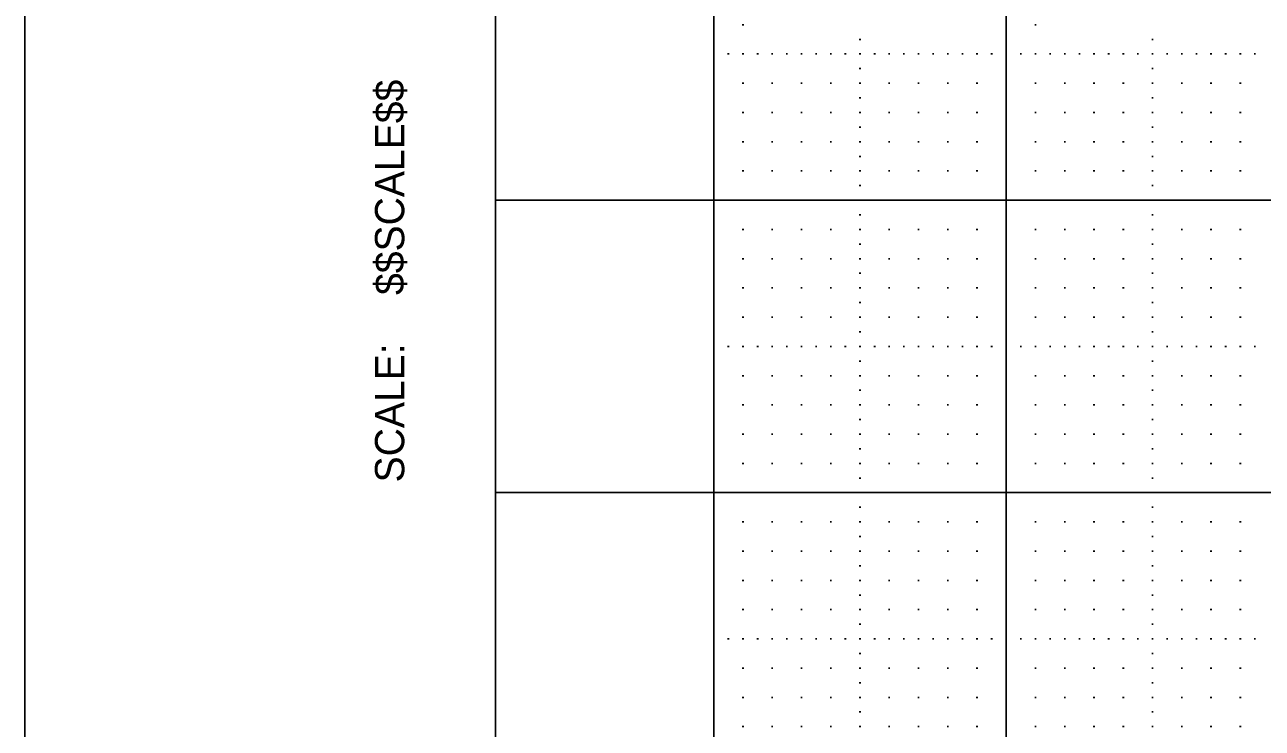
# Model space of a CAD drawing. Extents: x -1.3 to 32.7, y -0.7 to 21.3.
# Drawn here: x -1.263 to 2.967, y 2.487 to 4.893 of the extents above; entities that cross this region are included whole.
import ezdxf

# ---------------------------------------------------------------- set-up
doc = ezdxf.new("R2010")
doc.units = 0
for name, color, linetype in [('Level 1', 7, 'Continuous'), ('Level 5', 7, 'Continuous'), ('Level 63', 7, 'Continuous'), ('R_Border_Dark', 7, 'Continuous')]:
    doc.layers.add(name, color=color, linetype=linetype)

msp = doc.modelspace()

# ---------------------------------------------------------------- linework, layer by layer
at = {"layer": 'Level 1'}
for p, q in [((-1.263, 21.273), (-1.263, -0.727)), ((0.3463, -0.001), (0.3463, 20.545))]:
    msp.add_line(p, q, dxfattribs=at)
at = {"layer": 'Level 5'}
for p, q in [((1.1898, 4.893), (1.1948, 4.893)), ((2.1898, 4.893), (2.1948, 4.893)), ((1.5898, 4.843), (1.5948, 4.843)), ((2.5898, 4.843), (2.5948, 4.843)), ((1.1398, 4.793), (1.1448, 4.793)), ((1.1898, 4.793), (1.1948, 4.793)), ((1.2398, 4.793), (1.2448, 4.793)), ((1.2898, 4.793), (1.2948, 4.793)), ((1.3398, 4.793), (1.3448, 4.793)), ((1.3898, 4.793), (1.3948, 4.793)), ((1.4398, 4.793), (1.4448, 4.793)), ((1.4898, 4.793), (1.4948, 4.793)), ((1.5398, 4.793), (1.5448, 4.793)), ((1.5898, 4.793), (1.5948, 4.793)), ((1.6398, 4.793), (1.6448, 4.793)), ((1.6898, 4.793), (1.6948, 4.793)), ((1.7398, 4.793), (1.7448, 4.793)), ((1.7898, 4.793), (1.7948, 4.793)), ((1.8398, 4.793), (1.8448, 4.793)), ((1.8898, 4.793), (1.8948, 4.793)), ((1.9398, 4.793), (1.9448, 4.793)), ((1.9898, 4.793), (1.9948, 4.793)), ((2.0398, 4.793), (2.0448, 4.793)), ((2.1398, 4.793), (2.1448, 4.793)), ((2.1898, 4.793), (2.1948, 4.793)), ((2.2398, 4.793), (2.2448, 4.793)), ((2.2898, 4.793), (2.2948, 4.793)), ((2.3398, 4.793), (2.3448, 4.793)), ((2.3898, 4.793), (2.3948, 4.793)), ((2.4398, 4.793), (2.4448, 4.793)), ((2.4898, 4.793), (2.4948, 4.793)), ((2.5398, 4.793), (2.5448, 4.793)), ((2.5898, 4.793), (2.5948, 4.793)), ((2.6398, 4.793), (2.6448, 4.793)), ((2.6898, 4.793), (2.6948, 4.793)), ((2.7398, 4.793), (2.7448, 4.793)), ((2.7898, 4.793), (2.7948, 4.793)), ((2.8398, 4.793), (2.8448, 4.793)), ((2.8898, 4.793), (2.8948, 4.793)), ((2.9398, 4.793), (2.9448, 4.793)), ((1.5898, 4.743), (1.5948, 4.743)), ((2.5898, 4.743), (2.5948, 4.743)), ((1.1898, 4.693), (1.1948, 4.693)), ((1.2898, 4.693), (1.2948, 4.693)), ((1.3898, 4.693), (1.3948, 4.693)), ((1.4898, 4.693), (1.4948, 4.693)), ((1.5898, 4.693), (1.5948, 4.693)), ((1.6898, 4.693), (1.6948, 4.693)), ((1.7898, 4.693), (1.7948, 4.693)), ((1.8898, 4.693), (1.8948, 4.693)), ((1.9898, 4.693), (1.9948, 4.693)), ((2.1898, 4.693), (2.1948, 4.693)), ((2.2898, 4.693), (2.2948, 4.693)), ((2.3898, 4.693), (2.3948, 4.693)), ((2.4898, 4.693), (2.4948, 4.693)), ((2.5898, 4.693), (2.5948, 4.693)), ((2.6898, 4.693), (2.6948, 4.693)), ((2.7898, 4.693), (2.7948, 4.693)), ((2.8898, 4.693), (2.8948, 4.693)), ((1.5898, 4.643), (1.5948, 4.643)), ((2.5898, 4.643), (2.5948, 4.643)), ((1.1898, 4.593), (1.1948, 4.593)), ((1.2898, 4.593), (1.2948, 4.593)), ((1.3898, 4.593), (1.3948, 4.593)), ((1.4898, 4.593), (1.4948, 4.593)), ((1.5898, 4.593), (1.5948, 4.593)), ((1.6898, 4.593), (1.6948, 4.593)), ((1.7898, 4.593), (1.7948, 4.593)), ((1.8898, 4.593), (1.8948, 4.593)), ((1.9898, 4.593), (1.9948, 4.593)), ((2.1898, 4.593), (2.1948, 4.593)), ((2.2898, 4.593), (2.2948, 4.593)), ((2.3898, 4.593), (2.3948, 4.593)), ((2.4898, 4.593), (2.4948, 4.593)), ((2.5898, 4.593), (2.5948, 4.593)), ((2.6898, 4.593), (2.6948, 4.593)), ((2.7898, 4.593), (2.7948, 4.593)), ((2.8898, 4.593), (2.8948, 4.593)), ((1.5898, 4.543), (1.5948, 4.543)), ((2.5898, 4.543), (2.5948, 4.543)), ((1.1898, 4.493), (1.1948, 4.493)), ((1.2898, 4.493), (1.2948, 4.493)), ((1.3898, 4.493), (1.3948, 4.493)), ((1.4898, 4.493), (1.4948, 4.493)), ((1.5898, 4.493), (1.5948, 4.493)), ((1.6898, 4.493), (1.6948, 4.493)), ((1.7898, 4.493), (1.7948, 4.493)), ((1.8898, 4.493), (1.8948, 4.493)), ((1.9898, 4.493), (1.9948, 4.493)), ((2.1898, 4.493), (2.1948, 4.493)), ((2.2898, 4.493), (2.2948, 4.493)), ((2.3898, 4.493), (2.3948, 4.493)), ((2.4898, 4.493), (2.4948, 4.493)), ((2.5898, 4.493), (2.5948, 4.493)), ((2.6898, 4.493), (2.6948, 4.493)), ((2.7898, 4.493), (2.7948, 4.493)), ((2.8898, 4.493), (2.8948, 4.493)), ((1.5898, 4.443), (1.5948, 4.443)), ((2.5898, 4.443), (2.5948, 4.443)), ((1.1898, 4.393), (1.1948, 4.393)), ((1.2898, 4.393), (1.2948, 4.393)), ((1.3898, 4.393), (1.3948, 4.393)), ((1.4898, 4.393), (1.4948, 4.393)), ((1.5898, 4.393), (1.5948, 4.393)), ((1.6898, 4.393), (1.6948, 4.393)), ((1.7898, 4.393), (1.7948, 4.393)), ((1.8898, 4.393), (1.8948, 4.393)), ((1.9898, 4.393), (1.9948, 4.393)), ((2.1898, 4.393), (2.1948, 4.393)), ((2.2898, 4.393), (2.2948, 4.393)), ((2.3898, 4.393), (2.3948, 4.393)), ((2.4898, 4.393), (2.4948, 4.393)), ((2.5898, 4.393), (2.5948, 4.393)), ((2.6898, 4.393), (2.6948, 4.393)), ((2.7898, 4.393), (2.7948, 4.393)), ((2.8898, 4.393), (2.8948, 4.393)), ((1.5898, 4.343), (1.5948, 4.343)), ((2.5898, 4.343), (2.5948, 4.343)), ((1.5898, 4.243), (1.5948, 4.243)), ((2.5898, 4.243), (2.5948, 4.243)), ((1.1898, 4.193), (1.1948, 4.193)), ((1.2898, 4.193), (1.2948, 4.193)), ((1.3898, 4.193), (1.3948, 4.193)), ((1.4898, 4.193), (1.4948, 4.193)), ((1.5898, 4.193), (1.5948, 4.193)), ((1.6898, 4.193), (1.6948, 4.193)), ((1.7898, 4.193), (1.7948, 4.193)), ((1.8898, 4.193), (1.8948, 4.193)), ((1.9898, 4.193), (1.9948, 4.193)), ((2.1898, 4.193), (2.1948, 4.193)), ((2.2898, 4.193), (2.2948, 4.193)), ((2.3898, 4.193), (2.3948, 4.193)), ((2.4898, 4.193), (2.4948, 4.193)), ((2.5898, 4.193), (2.5948, 4.193)), ((2.6898, 4.193), (2.6948, 4.193)), ((2.7898, 4.193), (2.7948, 4.193)), ((2.8898, 4.193), (2.8948, 4.193)), ((1.5898, 4.143), (1.5948, 4.143)), ((2.5898, 4.143), (2.5948, 4.143)), ((1.1898, 4.093), (1.1948, 4.093)), ((1.2898, 4.093), (1.2948, 4.093)), ((1.3898, 4.093), (1.3948, 4.093)), ((1.4898, 4.093), (1.4948, 4.093)), ((1.5898, 4.093), (1.5948, 4.093)), ((1.6898, 4.093), (1.6948, 4.093)), ((1.7898, 4.093), (1.7948, 4.093)), ((1.8898, 4.093), (1.8948, 4.093)), ((1.9898, 4.093), (1.9948, 4.093)), ((2.1898, 4.093), (2.1948, 4.093)), ((2.2898, 4.093), (2.2948, 4.093)), ((2.3898, 4.093), (2.3948, 4.093)), ((2.4898, 4.093), (2.4948, 4.093)), ((2.5898, 4.093), (2.5948, 4.093)), ((2.6898, 4.093), (2.6948, 4.093)), ((2.7898, 4.093), (2.7948, 4.093)), ((2.8898, 4.093), (2.8948, 4.093)), ((1.5898, 4.043), (1.5948, 4.043)), ((2.5898, 4.043), (2.5948, 4.043)), ((1.1898, 3.993), (1.1948, 3.993)), ((1.2898, 3.993), (1.2948, 3.993)), ((1.3898, 3.993), (1.3948, 3.993)), ((1.4898, 3.993), (1.4948, 3.993)), ((1.5898, 3.993), (1.5948, 3.993)), ((1.6898, 3.993), (1.6948, 3.993)), ((1.7898, 3.993), (1.7948, 3.993)), ((1.8898, 3.993), (1.8948, 3.993)), ((1.9898, 3.993), (1.9948, 3.993)), ((2.1898, 3.993), (2.1948, 3.993)), ((2.2898, 3.993), (2.2948, 3.993)), ((2.3898, 3.993), (2.3948, 3.993)), ((2.4898, 3.993), (2.4948, 3.993)), ((2.5898, 3.993), (2.5948, 3.993)), ((2.6898, 3.993), (2.6948, 3.993)), ((2.7898, 3.993), (2.7948, 3.993)), ((2.8898, 3.993), (2.8948, 3.993)), ((1.5898, 3.943), (1.5948, 3.943)), ((2.5898, 3.943), (2.5948, 3.943)), ((1.1898, 3.893), (1.1948, 3.893)), ((1.2898, 3.893), (1.2948, 3.893)), ((1.3898, 3.893), (1.3948, 3.893)), ((1.4898, 3.893), (1.4948, 3.893)), ((1.5898, 3.893), (1.5948, 3.893)), ((1.6898, 3.893), (1.6948, 3.893)), ((1.7898, 3.893), (1.7948, 3.893)), ((1.8898, 3.893), (1.8948, 3.893)), ((1.9898, 3.893), (1.9948, 3.893)), ((2.1898, 3.893), (2.1948, 3.893)), ((2.2898, 3.893), (2.2948, 3.893)), ((2.3898, 3.893), (2.3948, 3.893)), ((2.4898, 3.893), (2.4948, 3.893)), ((2.5898, 3.893), (2.5948, 3.893)), ((2.6898, 3.893), (2.6948, 3.893)), ((2.7898, 3.893), (2.7948, 3.893)), ((2.8898, 3.893), (2.8948, 3.893)), ((1.5898, 3.843), (1.5948, 3.843)), ((2.5898, 3.843), (2.5948, 3.843)), ((1.1398, 3.793), (1.1448, 3.793)), ((1.1898, 3.793), (1.1948, 3.793)), ((1.2398, 3.793), (1.2448, 3.793)), ((1.2898, 3.793), (1.2948, 3.793)), ((1.3398, 3.793), (1.3448, 3.793)), ((1.3898, 3.793), (1.3948, 3.793)), ((1.4398, 3.793), (1.4448, 3.793)), ((1.4898, 3.793), (1.4948, 3.793)), ((1.5398, 3.793), (1.5448, 3.793)), ((1.5898, 3.793), (1.5948, 3.793)), ((1.6398, 3.793), (1.6448, 3.793)), ((1.6898, 3.793), (1.6948, 3.793)), ((1.7398, 3.793), (1.7448, 3.793)), ((1.7898, 3.793), (1.7948, 3.793)), ((1.8398, 3.793), (1.8448, 3.793)), ((1.8898, 3.793), (1.8948, 3.793)), ((1.9398, 3.793), (1.9448, 3.793)), ((1.9898, 3.793), (1.9948, 3.793)), ((2.0398, 3.793), (2.0448, 3.793)), ((2.1398, 3.793), (2.1448, 3.793)), ((2.1898, 3.793), (2.1948, 3.793)), ((2.2398, 3.793), (2.2448, 3.793)), ((2.2898, 3.793), (2.2948, 3.793)), ((2.3398, 3.793), (2.3448, 3.793)), ((2.3898, 3.793), (2.3948, 3.793)), ((2.4398, 3.793), (2.4448, 3.793)), ((2.4898, 3.793), (2.4948, 3.793)), ((2.5398, 3.793), (2.5448, 3.793)), ((2.5898, 3.793), (2.5948, 3.793)), ((2.6398, 3.793), (2.6448, 3.793)), ((2.6898, 3.793), (2.6948, 3.793)), ((2.7398, 3.793), (2.7448, 3.793)), ((2.7898, 3.793), (2.7948, 3.793)), ((2.8398, 3.793), (2.8448, 3.793)), ((2.8898, 3.793), (2.8948, 3.793)), ((2.9398, 3.793), (2.9448, 3.793)), ((1.5898, 3.743), (1.5948, 3.743)), ((2.5898, 3.743), (2.5948, 3.743)), ((1.1898, 3.693), (1.1948, 3.693)), ((1.2898, 3.693), (1.2948, 3.693)), ((1.3898, 3.693), (1.3948, 3.693)), ((1.4898, 3.693), (1.4948, 3.693)), ((1.5898, 3.693), (1.5948, 3.693)), ((1.6898, 3.693), (1.6948, 3.693)), ((1.7898, 3.693), (1.7948, 3.693)), ((1.8898, 3.693), (1.8948, 3.693)), ((1.9898, 3.693), (1.9948, 3.693)), ((2.1898, 3.693), (2.1948, 3.693)), ((2.2898, 3.693), (2.2948, 3.693)), ((2.3898, 3.693), (2.3948, 3.693)), ((2.4898, 3.693), (2.4948, 3.693)), ((2.5898, 3.693), (2.5948, 3.693)), ((2.6898, 3.693), (2.6948, 3.693)), ((2.7898, 3.693), (2.7948, 3.693)), ((2.8898, 3.693), (2.8948, 3.693)), ((1.5898, 3.643), (1.5948, 3.643)), ((2.5898, 3.643), (2.5948, 3.643)), ((1.1898, 3.593), (1.1948, 3.593)), ((1.2898, 3.593), (1.2948, 3.593)), ((1.3898, 3.593), (1.3948, 3.593)), ((1.4898, 3.593), (1.4948, 3.593)), ((1.5898, 3.593), (1.5948, 3.593)), ((1.6898, 3.593), (1.6948, 3.593)), ((1.7898, 3.593), (1.7948, 3.593)), ((1.8898, 3.593), (1.8948, 3.593)), ((1.9898, 3.593), (1.9948, 3.593)), ((2.1898, 3.593), (2.1948, 3.593)), ((2.2898, 3.593), (2.2948, 3.593)), ((2.3898, 3.593), (2.3948, 3.593)), ((2.4898, 3.593), (2.4948, 3.593)), ((2.5898, 3.593), (2.5948, 3.593)), ((2.6898, 3.593), (2.6948, 3.593)), ((2.7898, 3.593), (2.7948, 3.593)), ((2.8898, 3.593), (2.8948, 3.593)), ((1.5898, 3.543), (1.5948, 3.543)), ((2.5898, 3.543), (2.5948, 3.543)), ((1.1898, 3.493), (1.1948, 3.493)), ((1.2898, 3.493), (1.2948, 3.493)), ((1.3898, 3.493), (1.3948, 3.493)), ((1.4898, 3.493), (1.4948, 3.493)), ((1.5898, 3.493), (1.5948, 3.493)), ((1.6898, 3.493), (1.6948, 3.493)), ((1.7898, 3.493), (1.7948, 3.493)), ((1.8898, 3.493), (1.8948, 3.493)), ((1.9898, 3.493), (1.9948, 3.493)), ((2.1898, 3.493), (2.1948, 3.493)), ((2.2898, 3.493), (2.2948, 3.493)), ((2.3898, 3.493), (2.3948, 3.493)), ((2.4898, 3.493), (2.4948, 3.493)), ((2.5898, 3.493), (2.5948, 3.493)), ((2.6898, 3.493), (2.6948, 3.493)), ((2.7898, 3.493), (2.7948, 3.493)), ((2.8898, 3.493), (2.8948, 3.493)), ((1.5898, 3.443), (1.5948, 3.443)), ((2.5898, 3.443), (2.5948, 3.443)), ((1.1898, 3.393), (1.1948, 3.393)), ((1.2898, 3.393), (1.2948, 3.393)), ((1.3898, 3.393), (1.3948, 3.393)), ((1.4898, 3.393), (1.4948, 3.393)), ((1.5898, 3.393), (1.5948, 3.393)), ((1.6898, 3.393), (1.6948, 3.393)), ((1.7898, 3.393), (1.7948, 3.393)), ((1.8898, 3.393), (1.8948, 3.393)), ((1.9898, 3.393), (1.9948, 3.393)), ((2.1898, 3.393), (2.1948, 3.393)), ((2.2898, 3.393), (2.2948, 3.393)), ((2.3898, 3.393), (2.3948, 3.393)), ((2.4898, 3.393), (2.4948, 3.393)), ((2.5898, 3.393), (2.5948, 3.393)), ((2.6898, 3.393), (2.6948, 3.393)), ((2.7898, 3.393), (2.7948, 3.393)), ((2.8898, 3.393), (2.8948, 3.393)), ((1.5898, 3.343), (1.5948, 3.343)), ((2.5898, 3.343), (2.5948, 3.343)), ((1.5898, 3.243), (1.5948, 3.243)), ((2.5898, 3.243), (2.5948, 3.243)), ((1.1898, 3.193), (1.1948, 3.193)), ((1.2898, 3.193), (1.2948, 3.193)), ((1.3898, 3.193), (1.3948, 3.193)), ((1.4898, 3.193), (1.4948, 3.193)), ((1.5898, 3.193), (1.5948, 3.193)), ((1.6898, 3.193), (1.6948, 3.193)), ((1.7898, 3.193), (1.7948, 3.193)), ((1.8898, 3.193), (1.8948, 3.193)), ((1.9898, 3.193), (1.9948, 3.193)), ((2.1898, 3.193), (2.1948, 3.193)), ((2.2898, 3.193), (2.2948, 3.193)), ((2.3898, 3.193), (2.3948, 3.193)), ((2.4898, 3.193), (2.4948, 3.193)), ((2.5898, 3.193), (2.5948, 3.193)), ((2.6898, 3.193), (2.6948, 3.193)), ((2.7898, 3.193), (2.7948, 3.193)), ((2.8898, 3.193), (2.8948, 3.193)), ((1.5898, 3.143), (1.5948, 3.143)), ((2.5898, 3.143), (2.5948, 3.143)), ((1.1898, 3.093), (1.1948, 3.093)), ((1.2898, 3.093), (1.2948, 3.093)), ((1.3898, 3.093), (1.3948, 3.093)), ((1.4898, 3.093), (1.4948, 3.093)), ((1.5898, 3.093), (1.5948, 3.093)), ((1.6898, 3.093), (1.6948, 3.093)), ((1.7898, 3.093), (1.7948, 3.093)), ((1.8898, 3.093), (1.8948, 3.093)), ((1.9898, 3.093), (1.9948, 3.093)), ((2.1898, 3.093), (2.1948, 3.093)), ((2.2898, 3.093), (2.2948, 3.093)), ((2.3898, 3.093), (2.3948, 3.093)), ((2.4898, 3.093), (2.4948, 3.093)), ((2.5898, 3.093), (2.5948, 3.093)), ((2.6898, 3.093), (2.6948, 3.093)), ((2.7898, 3.093), (2.7948, 3.093)), ((2.8898, 3.093), (2.8948, 3.093)), ((1.5898, 3.043), (1.5948, 3.043)), ((2.5898, 3.043), (2.5948, 3.043)), ((1.1898, 2.993), (1.1948, 2.993)), ((1.2898, 2.993), (1.2948, 2.993)), ((1.3898, 2.993), (1.3948, 2.993)), ((1.4898, 2.993), (1.4948, 2.993)), ((1.5898, 2.993), (1.5948, 2.993)), ((1.6898, 2.993), (1.6948, 2.993)), ((1.7898, 2.993), (1.7948, 2.993)), ((1.8898, 2.993), (1.8948, 2.993)), ((1.9898, 2.993), (1.9948, 2.993)), ((2.1898, 2.993), (2.1948, 2.993)), ((2.2898, 2.993), (2.2948, 2.993)), ((2.3898, 2.993), (2.3948, 2.993)), ((2.4898, 2.993), (2.4948, 2.993)), ((2.5898, 2.993), (2.5948, 2.993)), ((2.6898, 2.993), (2.6948, 2.993)), ((2.7898, 2.993), (2.7948, 2.993)), ((2.8898, 2.993), (2.8948, 2.993)), ((1.5898, 2.943), (1.5948, 2.943)), ((2.5898, 2.943), (2.5948, 2.943)), ((1.1898, 2.893), (1.1948, 2.893)), ((1.2898, 2.893), (1.2948, 2.893)), ((1.3898, 2.893), (1.3948, 2.893)), ((1.4898, 2.893), (1.4948, 2.893)), ((1.5898, 2.893), (1.5948, 2.893)), ((1.6898, 2.893), (1.6948, 2.893)), ((1.7898, 2.893), (1.7948, 2.893)), ((1.8898, 2.893), (1.8948, 2.893)), ((1.9898, 2.893), (1.9948, 2.893)), ((2.1898, 2.893), (2.1948, 2.893)), ((2.2898, 2.893), (2.2948, 2.893)), ((2.3898, 2.893), (2.3948, 2.893)), ((2.4898, 2.893), (2.4948, 2.893)), ((2.5898, 2.893), (2.5948, 2.893)), ((2.6898, 2.893), (2.6948, 2.893)), ((2.7898, 2.893), (2.7948, 2.893)), ((2.8898, 2.893), (2.8948, 2.893)), ((1.5898, 2.843), (1.5948, 2.843)), ((2.5898, 2.843), (2.5948, 2.843)), ((1.1398, 2.793), (1.1448, 2.793)), ((1.1898, 2.793), (1.1948, 2.793)), ((1.2398, 2.793), (1.2448, 2.793)), ((1.2898, 2.793), (1.2948, 2.793)), ((1.3398, 2.793), (1.3448, 2.793)), ((1.3898, 2.793), (1.3948, 2.793)), ((1.4398, 2.793), (1.4448, 2.793)), ((1.4898, 2.793), (1.4948, 2.793)), ((1.5398, 2.793), (1.5448, 2.793)), ((1.5898, 2.793), (1.5948, 2.793)), ((1.6398, 2.793), (1.6448, 2.793)), ((1.6898, 2.793), (1.6948, 2.793)), ((1.7398, 2.793), (1.7448, 2.793)), ((1.7898, 2.793), (1.7948, 2.793)), ((1.8398, 2.793), (1.8448, 2.793)), ((1.8898, 2.793), (1.8948, 2.793)), ((1.9398, 2.793), (1.9448, 2.793)), ((1.9898, 2.793), (1.9948, 2.793)), ((2.0398, 2.793), (2.0448, 2.793)), ((2.1398, 2.793), (2.1448, 2.793)), ((2.1898, 2.793), (2.1948, 2.793)), ((2.2398, 2.793), (2.2448, 2.793)), ((2.2898, 2.793), (2.2948, 2.793)), ((2.3398, 2.793), (2.3448, 2.793)), ((2.3898, 2.793), (2.3948, 2.793)), ((2.4398, 2.793), (2.4448, 2.793)), ((2.4898, 2.793), (2.4948, 2.793)), ((2.5398, 2.793), (2.5448, 2.793)), ((2.5898, 2.793), (2.5948, 2.793)), ((2.6398, 2.793), (2.6448, 2.793)), ((2.6898, 2.793), (2.6948, 2.793)), ((2.7398, 2.793), (2.7448, 2.793)), ((2.7898, 2.793), (2.7948, 2.793)), ((2.8398, 2.793), (2.8448, 2.793)), ((2.8898, 2.793), (2.8948, 2.793)), ((2.9398, 2.793), (2.9448, 2.793)), ((1.5898, 2.743), (1.5948, 2.743)), ((2.5898, 2.743), (2.5948, 2.743)), ((1.1898, 2.693), (1.1948, 2.693)), ((1.2898, 2.693), (1.2948, 2.693)), ((1.3898, 2.693), (1.3948, 2.693)), ((1.4898, 2.693), (1.4948, 2.693)), ((1.5898, 2.693), (1.5948, 2.693)), ((1.6898, 2.693), (1.6948, 2.693)), ((1.7898, 2.693), (1.7948, 2.693)), ((1.8898, 2.693), (1.8948, 2.693)), ((1.9898, 2.693), (1.9948, 2.693)), ((2.1898, 2.693), (2.1948, 2.693)), ((2.2898, 2.693), (2.2948, 2.693)), ((2.3898, 2.693), (2.3948, 2.693)), ((2.4898, 2.693), (2.4948, 2.693)), ((2.5898, 2.693), (2.5948, 2.693)), ((2.6898, 2.693), (2.6948, 2.693)), ((2.7898, 2.693), (2.7948, 2.693)), ((2.8898, 2.693), (2.8948, 2.693)), ((1.5898, 2.643), (1.5948, 2.643)), ((2.5898, 2.643), (2.5948, 2.643)), ((1.1898, 2.593), (1.1948, 2.593)), ((1.2898, 2.593), (1.2948, 2.593)), ((1.3898, 2.593), (1.3948, 2.593)), ((1.4898, 2.593), (1.4948, 2.593)), ((1.5898, 2.593), (1.5948, 2.593)), ((1.6898, 2.593), (1.6948, 2.593)), ((1.7898, 2.593), (1.7948, 2.593)), ((1.8898, 2.593), (1.8948, 2.593)), ((1.9898, 2.593), (1.9948, 2.593)), ((2.1898, 2.593), (2.1948, 2.593)), ((2.2898, 2.593), (2.2948, 2.593)), ((2.3898, 2.593), (2.3948, 2.593)), ((2.4898, 2.593), (2.4948, 2.593)), ((2.5898, 2.593), (2.5948, 2.593)), ((2.6898, 2.593), (2.6948, 2.593)), ((2.7898, 2.593), (2.7948, 2.593)), ((2.8898, 2.593), (2.8948, 2.593)), ((1.5898, 2.543), (1.5948, 2.543)), ((2.5898, 2.543), (2.5948, 2.543)), ((1.1898, 2.493), (1.1948, 2.493)), ((1.2898, 2.493), (1.2948, 2.493)), ((1.3898, 2.493), (1.3948, 2.493)), ((1.4898, 2.493), (1.4948, 2.493)), ((1.5898, 2.493), (1.5948, 2.493)), ((1.6898, 2.493), (1.6948, 2.493)), ((1.7898, 2.493), (1.7948, 2.493)), ((1.8898, 2.493), (1.8948, 2.493)), ((1.9898, 2.493), (1.9948, 2.493)), ((2.1898, 2.493), (2.1948, 2.493)), ((2.2898, 2.493), (2.2948, 2.493)), ((2.3898, 2.493), (2.3948, 2.493)), ((2.4898, 2.493), (2.4948, 2.493)), ((2.5898, 2.493), (2.5948, 2.493)), ((2.6898, 2.493), (2.6948, 2.493)), ((2.7898, 2.493), (2.7948, 2.493)), ((2.8898, 2.493), (2.8948, 2.493))]:
    msp.add_line(p, q, dxfattribs=at)
at = {"layer": 'Level 63'}
msp.add_lwpolyline([(-1.263, -0.727), (32.737, -0.727), (32.737, 21.273), (-1.263, 21.273)], close=True, dxfattribs=at)
msp.add_lwpolyline([(31.0923, 10.293), (31.0923, 0.293), (1.0923, 0.293), (1.0923, 8.293)], dxfattribs=at)
at = {"layer": 'R_Border_Dark'}
for p, q in [((1.0923, 0.293), (1.0923, 10.293)), ((2.0923, 0.293), (2.0923, 10.293)), ((31.9643, 4.293), (0.3463, 4.293)), ((31.9643, 3.293), (0.3463, 3.293))]:
    msp.add_line(p, q, dxfattribs=at)
msp.add_lwpolyline([(31.0923, 10.293), (31.0923, 0.293), (1.0923, 0.293), (1.0923, 8.293)], dxfattribs=at)

# ---------------------------------------------------------------- texts
at = {"layer": 'Level 1'}
for s, p in [('$$SCALE$$', (0.0343, 3.969)), ('SCALE:', (0.0343, 3.328))]:
    msp.add_text(s, height=0.1, rotation=90, dxfattribs=at).set_placement(p)

doc.saveas('drawing.dxf')
